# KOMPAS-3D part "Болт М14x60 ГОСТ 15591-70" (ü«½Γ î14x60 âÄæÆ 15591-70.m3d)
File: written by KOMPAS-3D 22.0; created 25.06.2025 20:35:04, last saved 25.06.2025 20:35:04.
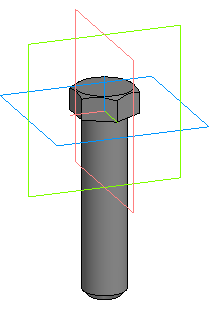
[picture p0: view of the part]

Document properties: Полное имя файла: D:\MY\WORK\MPEI\ППЭ_2025-2026\Варианты\Стандартные детали\Болт М14x60 ГОСТ 15591-70.m3d

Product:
- Part/product: Болт М14x60 ГОСТ 15591-70

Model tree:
1. Операция без истории:1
